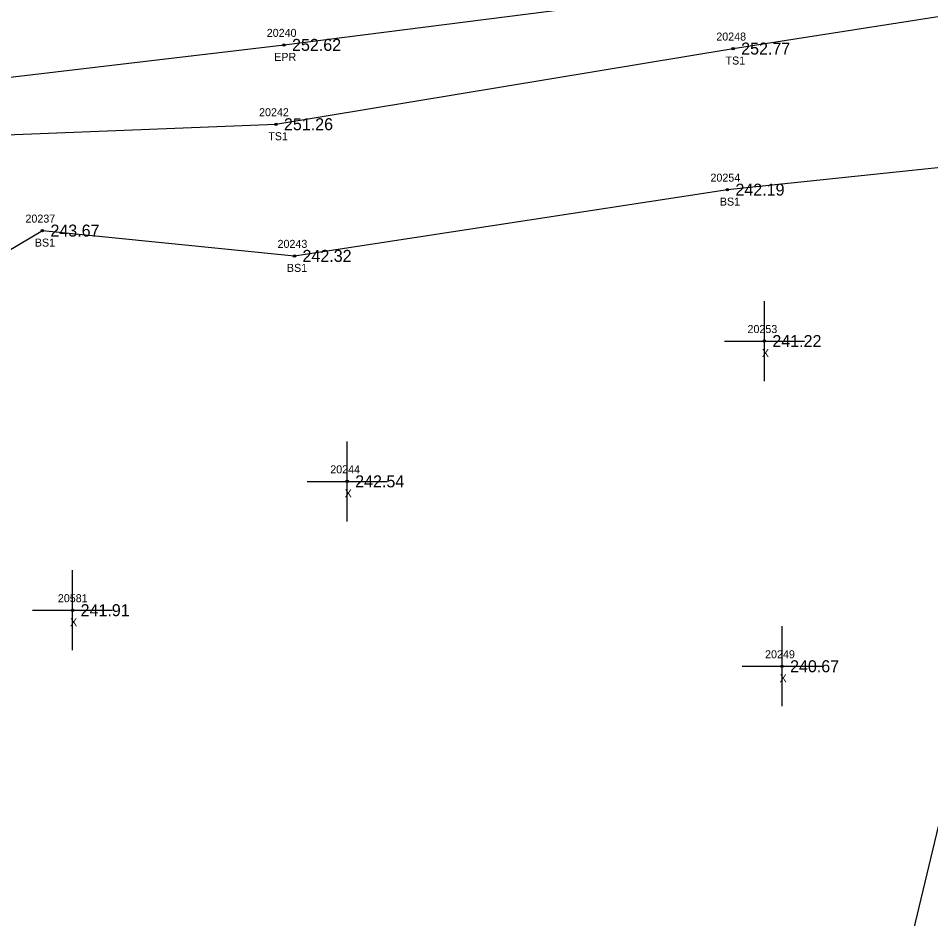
# Model space of a CAD drawing. Extents: x 2275563 to 2277161, y 1075719 to 1076412.
# Drawn here: x 2276399.9 to 2276514, y 1075959.9 to 1076072.5 of the extents above; entities that cross this region are included whole.
import ezdxf

# ---------------------------------------------------------------- set-up
doc = ezdxf.new("R2010")
doc.units = 0
for name, color, linetype in [('RD_DTM_BkLn2', 7, 'Continuous'), ('RD_DTM_BkLn_txCode', 7, 'Continuous'), ('RD_EX_Misc', 7, 'Continuous'), ('RD_EX_Misc_txCode', 7, 'Continuous'), ('RD_EX_Road', 7, 'Continuous'), ('RD_EX_Road_txCode', 7, 'Continuous'), ('RD_EX_TX_Misc_ELEV', 7, 'Continuous'), ('RD_EX_TX_Road_ELEV', 7, 'Continuous'), ('RD_SMD_Locator', 7, 'Continuous')]:
    doc.layers.add(name, color=color, linetype=linetype)

msp = doc.modelspace()

# ---------------------------------------------------------------- linework, layer by layer
at = {"layer": 'RD_DTM_BkLn2'}
for points in [[(2276381.23, 1076060.52), (2276384.72, 1076057.35), (2276432.14, 1076059.24), (2276489.29, 1076068.7), (2276538.36, 1076076.43), (2276580.68, 1076083.56), (2276626.16, 1076090.05), (2276659.02, 1076095.85)], [(2276373.09, 1076038.49), (2276389.65, 1076038.07), (2276402.95, 1076045.94), (2276434.46, 1076042.78), (2276488.57, 1076051.06), (2276535.54, 1076055.99), (2276577.32, 1076064.99)], [(2276519.11, 1075988.97), (2276497.82, 1075900.18), (2276501, 1075833.77), (2276548.94, 1075764.25)]]:
    msp.add_lwpolyline(points, dxfattribs=at)
at = {"layer": 'RD_EX_Misc'}
for p, q in [((2276493.19, 1076027.13), (2276493.19, 1076037.13)), ((2276488.19, 1076032.13), (2276498.19, 1076032.13)), ((2276441.04, 1076009.59), (2276441.04, 1076019.59)), ((2276436.04, 1076014.59), (2276446.04, 1076014.59)), ((2276406.72, 1075993.48), (2276406.72, 1076003.48)), ((2276401.72, 1075998.48), (2276411.72, 1075998.48)), ((2276495.4, 1075986.47), (2276495.4, 1075996.47)), ((2276490.4, 1075991.47), (2276500.4, 1075991.47))]:
    msp.add_line(p, q, dxfattribs=at)
at = {"layer": 'RD_EX_Road'}
msp.add_lwpolyline([(2276381.27, 1076063.04), (2276433.15, 1076069.16), (2276488.59, 1076076.23), (2276537.45, 1076083.34), (2276579.64, 1076090.09), (2276624.07, 1076098.24), (2276670.54, 1076107.46), (2276716.67, 1076118.09), (2276765.18, 1076130.28), (2276809.58, 1076142.25), (2276856.93, 1076156.58), (2276903.53, 1076171.63), (2276957.27, 1076189.46), (2277005.85, 1076206.01), (2277060.98, 1076225.07), (2277139.5, 1076252.36)], dxfattribs=at)
at = {"layer": 'RD_SMD_Locator'}
for centre in [(2276433.15, 1076069.16), (2276489.29, 1076068.7), (2276432.14, 1076059.24), (2276488.57, 1076051.06), (2276402.95, 1076045.94), (2276434.46, 1076042.78), (2276493.19, 1076032.13), (2276441.04, 1076014.59), (2276406.72, 1075998.48), (2276495.4, 1075991.47)]:
    msp.add_circle(centre, 0.15, dxfattribs=at)

# ---------------------------------------------------------------- texts
at = {"layer": 'RD_DTM_BkLn_txCode'}
for s, p in [('20248', (2276487.18, 1076069.7)), ('TS1', (2276488.33, 1076066.7)), ('20242', (2276430.03, 1076060.24)), ('TS1', (2276431.18, 1076057.24)), ('20254', (2276486.45, 1076052.06)), ('BS1', (2276487.62, 1076049.06)), ('20237', (2276400.83, 1076046.94)), ('BS1', (2276402, 1076043.94)), ('20243', (2276432.34, 1076043.78)), ('BS1', (2276433.51, 1076040.78))]:
    msp.add_text(s, height=1, dxfattribs=at).set_placement(p)
at = {"layer": 'RD_EX_Misc_txCode'}
for s, p in [('20253', (2276491.08, 1076033.13)), ('X', (2276492.88, 1076030.13)), ('20244', (2276438.93, 1076015.59)), ('X', (2276440.73, 1076012.59)), ('20581', (2276404.88, 1075999.48)), ('X', (2276406.4, 1075996.48)), ('20249', (2276493.28, 1075992.47)), ('X', (2276495.09, 1075989.47))]:
    msp.add_text(s, height=1, dxfattribs=at).set_placement(p)
at = {"layer": 'RD_EX_Road_txCode'}
for s, p in [('20240', (2276430.99, 1076070.16)), ('EPR', (2276431.92, 1076067.16))]:
    msp.add_text(s, height=1, dxfattribs=at).set_placement(p)
at = {"layer": 'RD_EX_TX_Misc_ELEV'}
for s, p in [('252.77', (2276490.29, 1076067.95)), ('251.26', (2276433.14, 1076058.49)), ('242.19', (2276489.57, 1076050.31)), ('243.67', (2276403.95, 1076045.19)), ('242.32', (2276435.46, 1076042.03)), ('241.22', (2276494.19, 1076031.38)), ('242.54', (2276442.04, 1076013.84)), ('241.91', (2276407.72, 1075997.73)), ('240.67', (2276496.4, 1075990.72))]:
    msp.add_text(s, height=1.5, dxfattribs=at).set_placement(p)
at = {"layer": 'RD_EX_TX_Road_ELEV'}
msp.add_text('252.62', height=1.5, dxfattribs=at).set_placement((2276434.15, 1076068.41))

doc.saveas('drawing.dxf')
